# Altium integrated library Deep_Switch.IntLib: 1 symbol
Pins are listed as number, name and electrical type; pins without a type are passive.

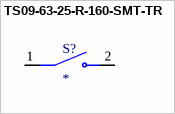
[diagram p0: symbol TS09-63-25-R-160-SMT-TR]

## TS09-63-25-R-160-SMT-TR
designator S?
MP: TS09-63-25-R-160-SMT-TR
footprint SW_TS09-63-25-R-160-SMT-TR
pins: 1, 2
